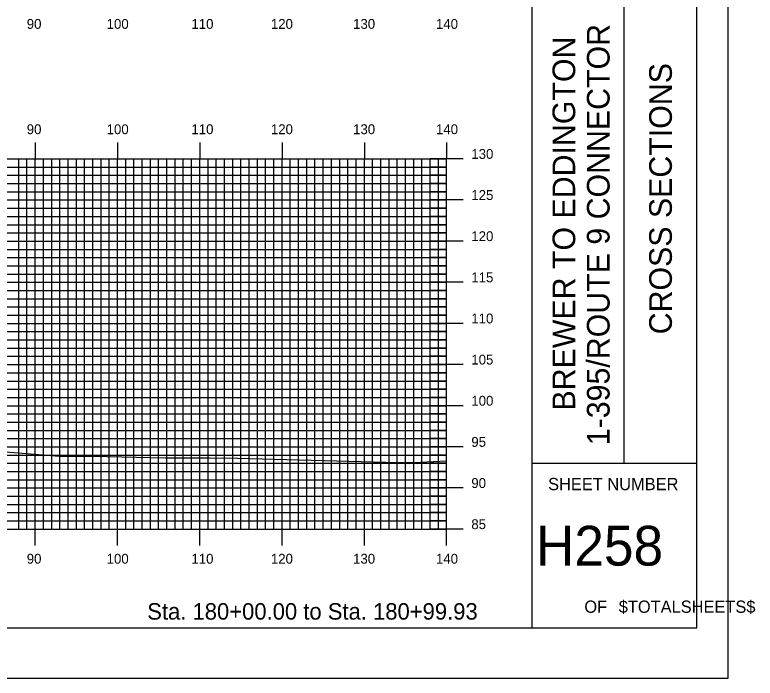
# Model space of a CAD drawing. Extents: x 1785795 to 1786139, y 442591 to 442811.
# Drawn here: x 1786048.6 to 1786138.5, y 442590.5 to 442671.2 of the extents above; entities that cross this region are included whole.
import ezdxf

# ---------------------------------------------------------------- set-up
doc = ezdxf.new("R2010")
doc.units = 0
for name, color, linetype in [('BORDER', 7, 'Continuous'), ('H_V ANNOTATION', 7, 'Continuous'), ('MAJOR', 7, 'Continuous'), ('MINOR', 7, 'Continuous'), ('PLOT BOUNDARY', 7, 'Continuous'), ('S_Roadway_Centerline', 7, 'Continuous')]:
    doc.layers.add(name, color=color, linetype=linetype)

msp = doc.modelspace()

# ---------------------------------------------------------------- linework, layer by layer
at = {"layer": 'BORDER'}
for p, q in [((1786111.452, 442596.665), (1786111.452, 442806.665)), ((1786122.634, 442616.671), (1786122.634, 442686.671)), ((1786111.452, 442616.671), (1786131.452, 442616.671))]:
    msp.add_line(p, q, dxfattribs=at)
msp.add_lwpolyline([(1785811.452, 442596.665), (1786131.452, 442596.665), (1786131.452, 442806.665), (1785811.452, 442806.665)], close=True, dxfattribs=at)
at = {"layer": 'MAJOR'}
for p, q in [((1786051.052, 442655.669), (1786051.052, 442653.665)), ((1786061.052, 442655.669), (1786061.052, 442653.665)), ((1786071.052, 442655.669), (1786071.052, 442653.665)), ((1786081.052, 442655.669), (1786081.052, 442653.665)), ((1786091.052, 442655.669), (1786091.052, 442653.665)), ((1786101.052, 442655.669), (1786101.052, 442653.665)), ((1785821.052, 442653.665), (1786101.052, 442653.665)), ((1785821.052, 442653.665), (1786101.052, 442653.665)), ((1786051.052, 442608.665), (1786051.052, 442653.665)), ((1786061.052, 442608.665), (1786061.052, 442653.665)), ((1786071.052, 442608.665), (1786071.052, 442653.665)), ((1786081.052, 442608.665), (1786081.052, 442653.665)), ((1786091.052, 442608.665), (1786091.052, 442653.665)), ((1786103.056, 442653.665), (1786099.048, 442653.665)), ((1786101.052, 442608.665), (1786101.052, 442653.665)), ((1786101.052, 442608.665), (1786101.052, 442653.665)), ((1785821.052, 442648.665), (1786101.052, 442648.665)), ((1786103.056, 442648.665), (1786099.048, 442648.665)), ((1785821.052, 442643.665), (1786101.052, 442643.665)), ((1786103.056, 442643.665), (1786099.048, 442643.665)), ((1785821.052, 442638.665), (1786101.052, 442638.665)), ((1786103.056, 442638.665), (1786099.048, 442638.665)), ((1785821.052, 442633.665), (1786101.052, 442633.665)), ((1786103.056, 442633.665), (1786099.048, 442633.665)), ((1785821.052, 442628.665), (1786101.052, 442628.665)), ((1786103.056, 442628.665), (1786099.048, 442628.665)), ((1785821.052, 442623.665), (1786101.052, 442623.665)), ((1786103.056, 442623.665), (1786099.048, 442623.665)), ((1785821.052, 442618.665), (1786101.052, 442618.665)), ((1786103.056, 442618.665), (1786099.048, 442618.665)), ((1785821.052, 442613.665), (1786101.052, 442613.665)), ((1786103.056, 442613.665), (1786099.048, 442613.665)), ((1785821.052, 442608.665), (1786101.052, 442608.665)), ((1785821.052, 442608.665), (1786101.052, 442608.665)), ((1786051.052, 442606.661), (1786051.052, 442608.665)), ((1786061.052, 442606.661), (1786061.052, 442608.665)), ((1786071.052, 442606.661), (1786071.052, 442608.665)), ((1786081.052, 442606.661), (1786081.052, 442608.665)), ((1786091.052, 442606.661), (1786091.052, 442608.665)), ((1786103.056, 442608.665), (1786099.048, 442608.665)), ((1786101.052, 442606.661), (1786101.052, 442608.665))]:
    msp.add_line(p, q, dxfattribs=at)
at = {"layer": 'MINOR'}
for p, q in [((1786049.052, 442608.665), (1786049.052, 442653.665)), ((1786050.052, 442608.665), (1786050.052, 442653.665)), ((1786052.052, 442608.665), (1786052.052, 442653.665)), ((1786053.052, 442608.665), (1786053.052, 442653.665)), ((1786054.052, 442608.665), (1786054.052, 442653.665)), ((1786055.052, 442608.665), (1786055.052, 442653.665)), ((1786056.052, 442608.665), (1786056.052, 442653.665)), ((1786057.052, 442608.665), (1786057.052, 442653.665)), ((1786058.052, 442608.665), (1786058.052, 442653.665)), ((1786059.052, 442608.665), (1786059.052, 442653.665)), ((1786060.052, 442608.665), (1786060.052, 442653.665)), ((1786062.052, 442608.665), (1786062.052, 442653.665)), ((1786063.052, 442608.665), (1786063.052, 442653.665)), ((1786064.052, 442608.665), (1786064.052, 442653.665)), ((1786065.052, 442608.665), (1786065.052, 442653.665)), ((1786066.052, 442608.665), (1786066.052, 442653.665)), ((1786067.052, 442608.665), (1786067.052, 442653.665)), ((1786068.052, 442608.665), (1786068.052, 442653.665)), ((1786069.052, 442608.665), (1786069.052, 442653.665)), ((1786070.052, 442608.665), (1786070.052, 442653.665)), ((1786072.052, 442608.665), (1786072.052, 442653.665)), ((1786073.052, 442608.665), (1786073.052, 442653.665)), ((1786074.052, 442608.665), (1786074.052, 442653.665)), ((1786075.052, 442608.665), (1786075.052, 442653.665)), ((1786076.052, 442608.665), (1786076.052, 442653.665)), ((1786077.052, 442608.665), (1786077.052, 442653.665)), ((1786078.052, 442608.665), (1786078.052, 442653.665)), ((1786079.052, 442608.665), (1786079.052, 442653.665)), ((1786080.052, 442608.665), (1786080.052, 442653.665)), ((1786082.052, 442608.665), (1786082.052, 442653.665)), ((1786083.052, 442608.665), (1786083.052, 442653.665)), ((1786084.052, 442608.665), (1786084.052, 442653.665)), ((1786085.052, 442608.665), (1786085.052, 442653.665)), ((1786086.052, 442608.665), (1786086.052, 442653.665)), ((1786087.052, 442608.665), (1786087.052, 442653.665)), ((1786088.052, 442608.665), (1786088.052, 442653.665)), ((1786089.052, 442608.665), (1786089.052, 442653.665)), ((1786090.052, 442608.665), (1786090.052, 442653.665)), ((1786092.052, 442608.665), (1786092.052, 442653.665)), ((1786093.052, 442608.665), (1786093.052, 442653.665)), ((1786094.052, 442608.665), (1786094.052, 442653.665)), ((1786095.052, 442608.665), (1786095.052, 442653.665)), ((1786096.052, 442608.665), (1786096.052, 442653.665)), ((1786097.052, 442608.665), (1786097.052, 442653.665)), ((1786098.052, 442608.665), (1786098.052, 442653.665)), ((1786099.052, 442608.665), (1786099.052, 442653.665)), ((1786100.052, 442608.665), (1786100.052, 442653.665)), ((1785821.052, 442652.665), (1786101.052, 442652.665)), ((1786101.052, 442652.665), (1786099.048, 442652.665)), ((1785821.052, 442651.665), (1786101.052, 442651.665)), ((1786101.052, 442651.665), (1786099.048, 442651.665)), ((1785821.052, 442650.665), (1786101.052, 442650.665)), ((1786101.052, 442650.665), (1786099.048, 442650.665)), ((1785821.052, 442649.665), (1786101.052, 442649.665)), ((1786101.052, 442649.665), (1786099.048, 442649.665)), ((1785821.052, 442647.665), (1786101.052, 442647.665)), ((1786101.052, 442647.665), (1786099.048, 442647.665)), ((1785821.052, 442646.665), (1786101.052, 442646.665)), ((1786101.052, 442646.665), (1786099.048, 442646.665)), ((1785821.052, 442645.665), (1786101.052, 442645.665)), ((1786101.052, 442645.665), (1786099.048, 442645.665)), ((1785821.052, 442644.665), (1786101.052, 442644.665)), ((1786101.052, 442644.665), (1786099.048, 442644.665)), ((1785821.052, 442642.665), (1786101.052, 442642.665)), ((1786101.052, 442642.665), (1786099.048, 442642.665)), ((1785821.052, 442641.665), (1786101.052, 442641.665)), ((1786101.052, 442641.665), (1786099.048, 442641.665)), ((1785821.052, 442640.665), (1786101.052, 442640.665)), ((1786101.052, 442640.665), (1786099.048, 442640.665)), ((1785821.052, 442639.665), (1786101.052, 442639.665)), ((1786101.052, 442639.665), (1786099.048, 442639.665)), ((1785821.052, 442637.665), (1786101.052, 442637.665)), ((1786101.052, 442637.665), (1786099.048, 442637.665)), ((1785821.052, 442636.665), (1786101.052, 442636.665)), ((1786101.052, 442636.665), (1786099.048, 442636.665)), ((1785821.052, 442635.665), (1786101.052, 442635.665)), ((1786101.052, 442635.665), (1786099.048, 442635.665)), ((1785821.052, 442634.665), (1786101.052, 442634.665)), ((1786101.052, 442634.665), (1786099.048, 442634.665)), ((1785821.052, 442632.665), (1786101.052, 442632.665)), ((1786101.052, 442632.665), (1786099.048, 442632.665)), ((1785821.052, 442631.665), (1786101.052, 442631.665)), ((1786101.052, 442631.665), (1786099.048, 442631.665)), ((1785821.052, 442630.665), (1786101.052, 442630.665)), ((1786101.052, 442630.665), (1786099.048, 442630.665)), ((1785821.052, 442629.665), (1786101.052, 442629.665)), ((1786101.052, 442629.665), (1786099.048, 442629.665)), ((1785821.052, 442627.665), (1786101.052, 442627.665)), ((1786101.052, 442627.665), (1786099.048, 442627.665)), ((1785821.052, 442626.665), (1786101.052, 442626.665)), ((1786101.052, 442626.665), (1786099.048, 442626.665)), ((1785821.052, 442625.665), (1786101.052, 442625.665)), ((1786101.052, 442625.665), (1786099.048, 442625.665)), ((1785821.052, 442624.665), (1786101.052, 442624.665)), ((1786101.052, 442624.665), (1786099.048, 442624.665)), ((1785821.052, 442622.665), (1786101.052, 442622.665)), ((1786101.052, 442622.665), (1786099.048, 442622.665)), ((1785821.052, 442621.665), (1786101.052, 442621.665)), ((1786101.052, 442621.665), (1786099.048, 442621.665)), ((1785821.052, 442620.665), (1786101.052, 442620.665)), ((1786101.052, 442620.665), (1786099.048, 442620.665)), ((1785821.052, 442619.665), (1786101.052, 442619.665)), ((1786101.052, 442619.665), (1786099.048, 442619.665)), ((1785821.052, 442617.665), (1786101.052, 442617.665)), ((1786101.052, 442617.665), (1786099.048, 442617.665)), ((1785821.052, 442616.665), (1786101.052, 442616.665)), ((1786101.052, 442616.665), (1786099.048, 442616.665)), ((1785821.052, 442615.665), (1786101.052, 442615.665)), ((1786101.052, 442615.665), (1786099.048, 442615.665)), ((1785821.052, 442614.665), (1786101.052, 442614.665)), ((1786101.052, 442614.665), (1786099.048, 442614.665)), ((1785821.052, 442612.665), (1786101.052, 442612.665)), ((1786101.052, 442612.665), (1786099.048, 442612.665)), ((1785821.052, 442611.665), (1786101.052, 442611.665)), ((1786101.052, 442611.665), (1786099.048, 442611.665)), ((1785821.052, 442610.665), (1786101.052, 442610.665)), ((1786101.052, 442610.665), (1786099.048, 442610.665)), ((1785821.052, 442609.665), (1786101.052, 442609.665)), ((1786101.052, 442609.665), (1786099.048, 442609.665))]:
    msp.add_line(p, q, dxfattribs=at)
at = {"layer": 'PLOT BOUNDARY'}
msp.add_lwpolyline([(1785795.265, 442590.547), (1786135.265, 442590.547), (1786135.265, 442810.547), (1785795.265, 442810.547)], close=True, dxfattribs=at)
at = {"layer": 'S_Roadway_Centerline'}
msp.add_lwpolyline([(1785931.687, 442622.463), (1785935.233, 442622.339), (1785943.333, 442622.252), (1785960.761, 442621.827), (1785964.38, 442621.652), (1785968.016, 442621.596), (1785970.948, 442621.241), (1785989.921, 442619.719), (1785991.344, 442619.692), (1786002.271, 442619.738), (1786013.496, 442619.205), (1786014.533, 442619.194), (1786015.752, 442619.155), (1786025.541, 442618.852), (1786034.235, 442618.896), (1786037.443, 442618.861), (1786053.969, 442617.544), (1786059.798, 442617.477), (1786066.871, 442617.312), (1786072.22, 442617.329), (1786075.65, 442617.277), (1786095.174, 442616.762), (1786097.059, 442616.773), (1786101.052, 442616.957)], dxfattribs=at)

# ---------------------------------------------------------------- texts
at = {"layer": 'BORDER'}
for s, p in [('1-395/ROUTE 9 CONNECTOR', (1786120.855, 442618.865)), ('BREWER TO EDDINGTON', (1786116.675, 442623.074)), ('CROSS SECTIONS', (1786128.421, 442632.339))]:
    msp.add_text(s, height=2.75575, rotation=90, dxfattribs=at).set_placement(p)
for s, height, p in [('SHEET NUMBER', 1.49054, (1786113.383, 442613.398)), ('H258', 4.8388, (1786111.891, 442604.23)), ('OF', 1.4905, (1786117.786, 442598.491)), ('$TOTALSHEETS$', 1.49054, (1786121.965, 442598.491))]:
    msp.add_text(s, height=height, dxfattribs=at).set_placement(p)
at = {"layer": 'H_V ANNOTATION'}
for s, height, p in [('90', 1.2, (1786050.024, 442669.465)), ('100', 1.2, (1786059.735, 442669.465)), ('110', 1.2, (1786070.035, 442669.465)), ('120', 1.2, (1786079.692, 442669.465)), ('130', 1.2, (1786089.682, 442669.465)), ('140', 1.2, (1786099.757, 442669.465)), ('90', 1.2, (1786050.024, 442656.665)), ('100', 1.2, (1786059.735, 442656.665)), ('110', 1.2, (1786070.035, 442656.665)), ('120', 1.2, (1786079.692, 442656.665)), ('130', 1.2, (1786089.682, 442656.665)), ('140', 1.2, (1786099.757, 442656.665)), ('130', 1.2, (1786104.052, 442653.665)), ('125', 1.2, (1786104.052, 442648.665)), ('120', 1.2, (1786104.052, 442643.665)), ('115', 1.2, (1786104.052, 442638.665)), ('110', 1.2, (1786104.052, 442633.665)), ('105', 1.2, (1786104.052, 442628.665)), ('100', 1.2, (1786104.052, 442623.665)), ('95', 1.2, (1786104.052, 442618.665)), ('90', 1.2, (1786104.052, 442613.665)), ('85', 1.2, (1786104.052, 442608.665)), ('90', 1.2, (1786050.024, 442604.465)), ('100', 1.2, (1786059.735, 442604.465)), ('110', 1.2, (1786070.035, 442604.465)), ('120', 1.2, (1786079.692, 442604.465)), ('130', 1.2, (1786089.682, 442604.465)), ('140', 1.2, (1786099.757, 442604.465)), ('Sta. 180+00.00 to Sta. 180+99.93', 2.0004, (1786064.666, 442597.665))]:
    msp.add_text(s, height=height, dxfattribs=at).set_placement(p)

doc.saveas('drawing.dxf')
